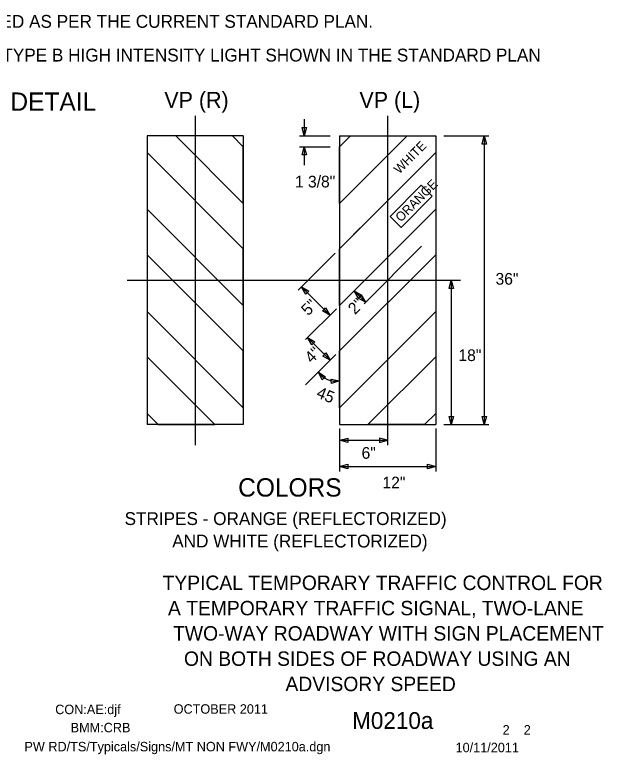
# Model space of a CAD drawing. Extents: x 16520 to 18479, y 5662 to 6927.
# Drawn here: x 18093.2 to 18478.6, y 5931.8 to 6415.8 of the extents above; entities that cross this region are included whole.
import ezdxf

# ---------------------------------------------------------------- set-up
doc = ezdxf.new("R2010")
doc.units = 0
for name, color, linetype in [('BORDER', 7, 'Continuous'), ('BORDER_SIGNAL_WO', 7, 'Continuous'), ('TRAFFIC_SIGNS_PR', 7, 'Continuous'), ('TYPICAL_TEXT_DIMEN_PR', 7, 'Continuous')]:
    doc.layers.add(name, color=color, linetype=linetype)

msp = doc.modelspace()

# ---------------------------------------------------------------- linework, layer by layer
at = {"layer": 'TRAFFIC_SIGNS_PR'}
for p, q in [((18242.87, 6336.58), (18179.87, 6336.58)), ((18179.87, 6336.58), (18179.87, 6147.58)), ((18242.87, 6292.31), (18198.6, 6336.58)), ((18242.87, 6329.44), (18235.73, 6336.58)), ((18242.87, 6336.58), (18242.87, 6147.58)), ((18305.9, 6336.58), (18368.9, 6336.58)), ((18305.9, 6336.58), (18305.9, 6147.58)), ((18305.9, 6329.44), (18313.04, 6336.58)), ((18305.9, 6292.31), (18350.16, 6336.58)), ((18368.9, 6336.58), (18368.9, 6147.58)), ((18242.87, 6262.61), (18179.87, 6325.61)), ((18305.9, 6262.61), (18368.9, 6325.61)), ((18242.87, 6225.49), (18179.87, 6288.49)), ((18305.9, 6225.49), (18368.9, 6288.49)), ((18315.18, 6271.9), (18324.46, 6281.18)), ((18242.87, 6195.79), (18179.87, 6258.79)), ((18305.9, 6195.79), (18368.9, 6258.79)), ((18242.87, 6158.66), (18179.87, 6221.66)), ((18305.9, 6158.66), (18368.9, 6221.66)), ((18224.26, 6147.58), (18179.87, 6191.97)), ((18324.5, 6147.58), (18368.9, 6191.97)), ((18187.14, 6147.58), (18179.87, 6154.84)), ((18361.63, 6147.58), (18368.9, 6154.84)), ((18242.87, 6147.58), (18179.87, 6147.58)), ((18305.9, 6147.58), (18368.9, 6147.58))]:
    msp.add_line(p, q, dxfattribs=at)
for points in [[(18235.73, 6336.58), (18198.6, 6336.58), (18242.87, 6292.31), (18242.87, 6329.44)], [(18313.04, 6336.58), (18350.16, 6336.58), (18305.9, 6292.31), (18305.9, 6329.44)], [(18242.87, 6262.61), (18179.87, 6325.61), (18179.87, 6288.49), (18242.87, 6225.49)], [(18305.9, 6262.61), (18368.9, 6325.61), (18368.9, 6288.49), (18305.9, 6225.49)], [(18242.87, 6195.79), (18179.87, 6258.79), (18179.87, 6221.66), (18242.87, 6158.66)], [(18305.9, 6195.79), (18368.9, 6258.79), (18368.9, 6221.66), (18305.9, 6158.66)], [(18179.87, 6191.97), (18179.87, 6154.84), (18187.14, 6147.58), (18224.26, 6147.58)], [(18368.9, 6191.97), (18368.9, 6154.84), (18361.63, 6147.58), (18324.5, 6147.58)]]:
    msp.add_lwpolyline(points, close=True, dxfattribs=at)
at = {"layer": 'TYPICAL_TEXT_DIMEN_PR'}
for p, q in [((18211.37, 6349.7), (18211.37, 6134.18)), ((18282.8, 6347.43), (18282.8, 6336.58)), ((18337.4, 6349.7), (18337.4, 6134.18)), ((18282.8, 6336.58), (18281.35, 6341.96)), ((18281.35, 6341.96), (18282.8, 6341.96)), ((18282.8, 6341.96), (18284.24, 6341.96)), ((18284.24, 6341.96), (18282.8, 6336.58)), ((18279.65, 6336.58), (18299.8, 6336.58)), ((18374.27, 6336.58), (18403.69, 6336.58)), ((18399.32, 6331.19), (18400.76, 6336.58)), ((18400.76, 6336.58), (18400.76, 6147.58)), ((18400.76, 6336.58), (18402.2, 6331.19)), ((18400.76, 6331.19), (18399.32, 6331.19)), ((18402.2, 6331.19), (18400.76, 6331.19)), ((18279.65, 6329.44), (18299.8, 6329.44)), ((18281.35, 6324.05), (18282.8, 6329.44)), ((18282.8, 6329.44), (18282.8, 6317.37)), ((18282.8, 6329.44), (18284.24, 6324.05)), ((18282.8, 6324.05), (18281.35, 6324.05)), ((18284.24, 6324.05), (18282.8, 6324.05)), ((18321.95, 6226.63), (18359.67, 6264.35)), ((18278.78, 6235.5), (18302.97, 6259.69)), ((18166.74, 6242.08), (18385.17, 6242.08)), ((18377.66, 6236.69), (18379.1, 6242.08)), ((18379.1, 6242.08), (18379.1, 6147.58)), ((18379.1, 6242.08), (18380.54, 6236.69)), ((18299.6, 6219.19), (18281.03, 6237.75)), ((18283.82, 6232.93), (18281.03, 6237.75)), ((18281.03, 6237.75), (18285.86, 6234.97)), ((18284.84, 6233.95), (18283.82, 6232.93)), ((18285.86, 6234.97), (18284.84, 6233.95)), ((18322.97, 6227.65), (18315.52, 6235.11)), ((18318.31, 6230.28), (18315.52, 6235.11)), ((18315.52, 6235.11), (18320.35, 6232.32)), ((18379.1, 6236.69), (18377.66, 6236.69)), ((18380.54, 6236.69), (18379.1, 6236.69)), ((18318.15, 6230.44), (18319.17, 6231.46)), ((18322.97, 6227.65), (18318.15, 6230.44)), ((18319.33, 6231.3), (18318.31, 6230.28)), ((18319.17, 6231.46), (18320.19, 6232.48)), ((18320.35, 6232.32), (18319.33, 6231.3)), ((18320.19, 6232.48), (18322.97, 6227.65)), ((18295.79, 6223), (18296.81, 6224.02)), ((18296.81, 6224.02), (18299.6, 6219.19)), ((18283.62, 6203.21), (18303.84, 6223.43)), ((18294.77, 6221.98), (18295.79, 6223)), ((18299.6, 6219.19), (18294.77, 6221.98)), ((18299.8, 6189.69), (18284.95, 6204.54)), ((18287.74, 6199.71), (18284.95, 6204.54)), ((18284.95, 6204.54), (18289.78, 6201.75)), ((18288.76, 6200.73), (18287.74, 6199.71)), ((18289.78, 6201.75), (18288.76, 6200.73)), ((18283.62, 6173.52), (18303.5, 6193.4)), ((18294.97, 6192.48), (18295.99, 6193.5)), ((18299.8, 6189.69), (18294.97, 6192.48)), ((18295.99, 6193.5), (18297.01, 6194.52)), ((18297.01, 6194.52), (18299.8, 6189.69)), ((18294.5, 6176.97), (18292.1, 6182)), ((18292.1, 6182), (18296.69, 6178.84)), ((18295.6, 6177.9), (18294.5, 6176.97)), ((18296.69, 6178.84), (18295.6, 6177.9)), ((18300.52, 6175.93), (18300.43, 6177.37)), ((18300.43, 6177.37), (18305.9, 6176.29)), ((18300.62, 6174.49), (18300.52, 6175.93)), ((18305.9, 6176.29), (18300.62, 6174.49)), ((18379.1, 6147.58), (18377.66, 6152.96)), ((18377.66, 6152.96), (18379.1, 6152.96)), ((18379.1, 6152.96), (18380.54, 6152.96)), ((18380.54, 6152.96), (18379.1, 6147.58)), ((18400.76, 6147.58), (18399.32, 6152.96)), ((18399.32, 6152.96), (18400.76, 6152.96)), ((18400.76, 6152.96), (18402.2, 6152.96)), ((18402.2, 6152.96), (18400.76, 6147.58)), ((18374.27, 6147.58), (18403.69, 6147.58)), ((18305.9, 6144.95), (18305.9, 6116.97)), ((18368.9, 6144.95), (18368.9, 6116.97)), ((18305.9, 6137.32), (18311.28, 6138.76)), ((18305.9, 6137.32), (18337.4, 6137.32)), ((18311.28, 6135.88), (18305.9, 6137.32)), ((18311.28, 6138.76), (18311.28, 6137.32)), ((18311.28, 6137.32), (18311.28, 6135.88)), ((18337.4, 6137.32), (18332.01, 6138.76)), ((18332.01, 6138.76), (18332.01, 6137.32)), ((18332.01, 6137.32), (18332.01, 6135.88)), ((18332.01, 6135.88), (18337.4, 6137.32)), ((18305.9, 6120.16), (18311.28, 6121.61)), ((18305.9, 6120.16), (18368.9, 6120.16)), ((18311.28, 6118.72), (18305.9, 6120.16)), ((18311.28, 6121.61), (18311.28, 6120.16)), ((18311.28, 6120.16), (18311.28, 6118.72)), ((18363.51, 6120.16), (18363.51, 6121.61)), ((18363.51, 6121.61), (18368.9, 6120.16)), ((18368.9, 6120.16), (18363.51, 6118.72)), ((18363.51, 6118.72), (18363.51, 6120.16))]:
    msp.add_line(p, q, dxfattribs=at)
msp.add_lwpolyline([(18339.06, 6283.83), (18359.48, 6304.25), (18366.67, 6297.07), (18346.24, 6276.65)], close=True, dxfattribs=at)
msp.add_arc((18303.13, 6189.12), 13.12, 212.8393, 282.1565, dxfattribs=at)

# ---------------------------------------------------------------- texts
at = {"layer": 'BORDER'}
for s, p in [('TYPICAL TEMPORARY TRAFFIC CONTROL FOR', (18190.04, 6039.31)), ('A TEMPORARY TRAFFIC SIGNAL, TWO-LANE', (18193.56, 6022.76)), ('TWO-WAY ROADWAY WITH SIGN PLACEMENT', (18196.92, 6006.22)), ('ON BOTH SIDES OF ROADWAY USING AN', (18204.04, 5989.66)), ('ADVISORY SPEED', (18270.52, 5973.11))]:
    msp.add_text(s, height=9.4427, dxfattribs=at).set_placement(p)
at = {"layer": 'BORDER_SIGNAL_WO'}
for s, height, p in [('CON:AE:djf', 6.2, (18119.69, 5958.06)), ('    OCTOBER 2011    ', 6.2, (18188.08, 5958.34)), ('    M0210a    ', 11, (18297.86, 5948.38)), ('BMM:CRB   ', 6.2, (18129.81, 5946.17)), (' 2    2 ', 6.2, (18410.45, 5944.7)), ('PW RD/TS/Typicals/Signs/MT NON FWY/M0210a.dgn     ', 6.2, (18099.55, 5933.71)), ('10/11/2011    ', 6.2, (18381.93, 5933.13))]:
    msp.add_text(s, height=height, dxfattribs=at).set_placement(p)
at = {"layer": 'TYPICAL_TEXT_DIMEN_PR'}
for s, height, p in [('TEMPORARY CONCRETE BARRIER SHALL BE APPLIED AS PER THE CURRENT STANDARD PLAN.', 8.4, (17801.7, 6407.29)), ('VERTICAL PANELS SHALL BE USED IN LIEU OF THE TYPE B HIGH INTENSITY LIGHT SHOWN IN THE STANDARD PLAN ', 8.4, (17801.7, 6385.24)), ('SIGN DETAIL', 12, (18046.66, 6352.97)), ('VP (R)', 10.5, (18191.18, 6354.87)), ('VP (L)', 10.5, (18318.97, 6354.87)), ('1 3/8"', 7.654, (18276.72, 6302.8)), ('36"', 7.654, (18408.1, 6239.16)), ('18"', 7.654, (18383.8, 6189.17)), ('6"', 7.654, (18320.36, 6125.22)), ('COLORS', 12, (18239.52, 6100.47)), ('12"', 7.654, (18334.07, 6105.82)), ('STRIPES - ORANGE (REFLECTORIZED)', 8.4, (18165.13, 6081.85)), ('          AND WHITE (REFLECTORIZED)', 8.4, (18165.13, 6067.15))]:
    msp.add_text(s, height=height, dxfattribs=at).set_placement(p)
for s, height, rotation, p in [('WHITE', 6, 45, (18345.09, 6311.25)), ('ORANGE', 6, 45, (18346.12, 6279.81)), ('5"', 7.654, 45, (18285.36, 6218.39)), ('2"', 7.654, 45.0095, (18316.05, 6219.13)), ('4"', 7.654, 45, (18287.71, 6187.28)), ('45', 7.655, 337.5007, (18290.18, 6165.67))]:
    msp.add_text(s, height=height, rotation=rotation, dxfattribs=at).set_placement(p)

doc.saveas('drawing.dxf')
